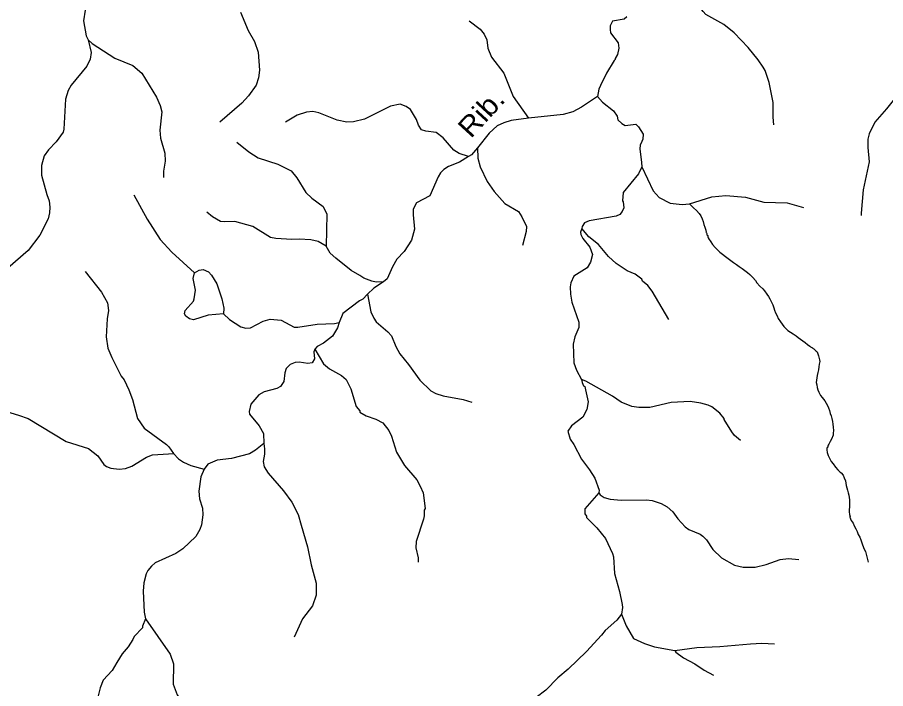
# Model space of a CAD drawing. Extents: x 346.5 to 372.4, y 7400.3 to 7428.2.
# Drawn here: x 364.068 to 367.524, y 7415.59 to 7418.262 of the extents above; entities that cross this region are included whole.
import ezdxf
from ezdxf.enums import TextEntityAlignment as Align

# ---------------------------------------------------------------- set-up
doc = ezdxf.new("R2010")
doc.units = 0
doc.header["$LTSCALE"] = 0.032
doc.layers.add('2', color=7, linetype='Continuous', lineweight=25)
doc.layers.add('7', color=7, linetype='Continuous', lineweight=25)
doc.layers.add('61', color=7, linetype='Continuous')

msp = doc.modelspace()

# ---------------------------------------------------------------- linework, layer by layer
at = {"layer": '2'}
msp.add_lwpolyline([(364.7726, 7417.2451), (364.7912, 7417.2562), (364.8071, 7417.2584), (364.8294, 7417.2489), (364.8408, 7417.2358), (364.8621, 7417.201), (364.8824, 7417.1415), (364.8905, 7417.1053), (364.8887, 7417.0818), (364.827, 7417.0764), (364.7693, 7417.0589), (364.7529, 7417.062), (364.7384, 7417.0726), (364.734, 7417.0828), (364.7354, 7417.0952), (364.7687, 7417.1326), (364.7722, 7417.142), (364.7766, 7417.1766), (364.7677, 7417.2224)], close=True, dxfattribs=at)
at = {"layer": '7'}
for points in [[(364.2254, 7418.6602), (364.2451, 7418.628), (364.2898, 7418.5793), (364.3089, 7418.5507), (364.3392, 7418.4885), (364.344, 7418.4726), (364.3551, 7418.4088), (364.3448, 7418.3195), (364.3376, 7418.2909), (364.332, 7418.2478), (364.3416, 7418.1881), (364.3499, 7418.173)], [(367.0791, 7417.8342), (367.0759, 7417.8653), (367.0759, 7417.9227), (367.0599, 7418.0024), (367.044, 7418.0502), (367.036, 7418.0645), (367.0169, 7418.0932), (366.9763, 7418.1418), (366.9213, 7418.2008), (366.8799, 7418.2335), (366.8089, 7418.2741), (366.7977, 7418.2861), (366.7762, 7418.3116), (366.7776, 7418.3454)], [(364.9568, 7418.2829), (364.9863, 7418.2096), (365.0126, 7418.1665), (365.0261, 7418.1235), (365.0325, 7418.0518), (365.0277, 7418.0215), (365.0182, 7417.9928), (364.9879, 7417.9498), (364.9616, 7417.9203), (364.8739, 7417.8454)], [(365.8669, 7418.2486), (365.91, 7418.2151), (365.9267, 7418.1952), (365.9363, 7418.1729), (365.941, 7418.1394), (365.9554, 7418.1044), (366.0048, 7418.0398), (366.0414, 7417.9466), (366.1029, 7417.8607)], [(366.4941, 7418.2645), (366.483, 7418.255), (366.4367, 7418.247), (366.4272, 7418.2287), (366.4272, 7418.2143), (366.4296, 7418.2), (366.4598, 7418.1609), (366.4622, 7418.1394), (366.4575, 7418.1147), (366.4479, 7418.0988), (366.4479, 7418.094), (366.4431, 7418.0908), (366.4136, 7418.0398), (366.3889, 7417.9912), (366.3825, 7417.9769), (366.3774, 7417.9478)], [(364.3499, 7418.173), (364.3615, 7418.1219), (364.3583, 7418.0964), (364.344, 7418.0677), (364.2826, 7417.9928), (364.2698, 7417.9705), (364.2595, 7417.937), (364.2531, 7417.8175), (364.2499, 7417.8047), (364.2228, 7417.7673), (364.1917, 7417.7354), (364.175, 7417.7107), (364.1638, 7417.6724), (364.1638, 7417.6342), (364.1854, 7417.5577), (364.1941, 7417.5322), (364.1973, 7417.5067), (364.1965, 7417.4843), (364.1909, 7417.4604), (364.1575, 7417.3951), (364.1113, 7417.3337), (364.03, 7417.2636)], [(364.3499, 7418.173), (364.3662, 7418.1584), (364.4555, 7418.1004), (364.5273, 7418.0701), (364.5631, 7418.0398), (364.6213, 7417.945), (364.6364, 7417.9115), (364.6436, 7417.886), (364.6348, 7417.8127), (364.638, 7417.7808), (364.6548, 7417.7218), (364.6564, 7417.69), (364.65, 7417.6501), (364.65, 7417.6254)], [(367.6362, 7418.1272), (367.613, 7418.0852), (367.5963, 7418.0279), (367.5716, 7417.9609), (367.5588, 7417.9378), (367.5278, 7417.8979), (367.4815, 7417.8454), (367.4584, 7417.7983), (367.4536, 7417.7776), (367.4536, 7417.7441), (367.4588, 7417.6867), (367.4345, 7417.5752), (367.4273, 7417.4828), (367.4266, 7417.474)], [(366.3774, 7417.9478), (366.314, 7417.9043), (366.279, 7417.8868), (366.2407, 7417.8756), (366.1029, 7417.8607)], [(366.3774, 7417.9478), (366.3969, 7417.9242), (366.4415, 7417.89), (366.4559, 7417.8693), (366.4582, 7417.8549), (366.4742, 7417.8398), (366.4878, 7417.8318), (366.5292, 7417.8374), (366.5411, 7417.827), (366.5595, 7417.7967), (366.5579, 7417.7768), (366.5531, 7417.7681), (366.5467, 7417.7537), (366.5451, 7417.7394), (366.5523, 7417.6843), (366.5536, 7417.6671)], [(365.8635, 7417.7084), (365.8271, 7417.7202), (365.8048, 7417.7338), (365.7633, 7417.7824), (365.7354, 7417.8039), (365.694, 7417.8087), (365.6772, 7417.8151), (365.6645, 7417.8334), (365.6573, 7417.8557), (365.6334, 7417.8948), (365.6159, 7417.9075), (365.592, 7417.9163), (365.5537, 7417.9091), (365.4501, 7417.8573), (365.4055, 7417.8461), (365.38, 7417.8453), (365.3417, 7417.8525), (365.2684, 7417.8828), (365.2445, 7417.8876), (365.219, 7417.8852), (365.1824, 7417.8732), (365.1353, 7417.8446)], [(366.1029, 7417.8607), (366.0335, 7417.8517), (366.004, 7417.843), (365.9785, 7417.831), (365.9466, 7417.8015), (365.8994, 7417.7432)], [(364.9417, 7417.7657), (364.9895, 7417.7274), (365.0261, 7417.7035), (365.1043, 7417.6772), (365.1584, 7417.6509), (365.1807, 7417.623), (365.2158, 7417.5648), (365.2397, 7417.5425), (365.2859, 7417.509), (365.3003, 7417.4788), (365.2974, 7417.351)], [(365.8994, 7417.7432), (365.8754, 7417.7156), (365.8635, 7417.7084)], [(365.8994, 7417.7432), (365.9012, 7417.7011), (365.9107, 7417.6676), (365.9386, 7417.6095), (365.9665, 7417.5688), (366.0088, 7417.521), (366.0622, 7417.4899), (366.0765, 7417.4684), (366.0941, 7417.4294), (366.0933, 7417.4094), (366.0781, 7417.3544)], [(365.8635, 7417.7084), (365.8279, 7417.6852), (365.7848, 7417.6684), (365.7657, 7417.6565), (365.7522, 7417.6437), (365.7434, 7417.6278), (365.7099, 7417.5521), (365.6565, 7417.5242), (365.6438, 7417.4987), (365.643, 7417.4764), (365.6493, 7417.419), (365.6366, 7417.376), (365.6071, 7417.3297), (365.5784, 7417.2995), (365.5609, 7417.2692), (365.5397, 7417.2213), (365.5253, 7417.2095)], [(366.5536, 7417.6671), (366.5406, 7417.6388), (366.479, 7417.5656), (366.4766, 7417.5314), (366.4798, 7417.5274), (366.4822, 7417.5043), (366.4758, 7417.4891), (366.4662, 7417.478), (366.4519, 7417.4708), (366.3443, 7417.4524), (366.3252, 7417.4437), (366.316, 7417.4302), (366.3146, 7417.422)], [(366.5536, 7417.6671), (366.5985, 7417.572), (366.6232, 7417.5449), (366.6663, 7417.5226), (366.7141, 7417.5178), (366.7433, 7417.5198)], [(364.5312, 7417.5553), (364.5846, 7417.4588), (364.6372, 7417.3775), (364.6827, 7417.3273), (364.7726, 7417.2451)], [(366.7433, 7417.5198), (366.8318, 7417.5484), (366.8878, 7417.5529), (366.9659, 7417.5465), (367.0392, 7417.5266), (367.1317, 7417.5242), (367.1978, 7417.5059)], [(366.7433, 7417.5198), (366.7595, 7417.5043), (366.7714, 7417.4939), (366.7818, 7417.482), (366.789, 7417.4716), (366.7938, 7417.4604), (366.7978, 7417.4493), (366.8009, 7417.4381), (366.8041, 7417.427), (366.8081, 7417.4158), (366.8097, 7417.4054), (366.8105, 7417.4047), (366.8129, 7417.4023), (366.8129, 7417.3967), (366.8161, 7417.3935), (366.8161, 7417.3863), (366.8193, 7417.3847), (366.8193, 7417.3823), (366.828, 7417.3688), (366.8352, 7417.3584), (366.8456, 7417.3457), (366.8543, 7417.3369), (366.8647, 7417.3281), (366.8751, 7417.3194), (366.8862, 7417.3106), (366.8974, 7417.3018), (366.9085, 7417.2939), (366.9189, 7417.2859), (366.9301, 7417.2787), (366.9412, 7417.2708), (366.9524, 7417.2628), (366.9643, 7417.2548), (366.9739, 7417.2468), (366.9834, 7417.2381), (366.9954, 7417.2269), (367.0057, 7417.2142), (367.0121, 7417.2054), (367.0233, 7417.1927), (367.0352, 7417.1815), (367.0424, 7417.1735), (367.0512, 7417.16), (367.0575, 7417.1512), (367.0631, 7417.1417), (367.0695, 7417.1281), (367.0751, 7417.1178), (367.0791, 7417.1066), (367.0823, 7417.097), (367.0862, 7417.0859), (367.0918, 7417.0747), (367.0966, 7417.0636), (367.1054, 7417.0508), (367.1117, 7417.0412), (367.1189, 7417.0317), (367.1269, 7417.0237), (367.1349, 7417.0157), (367.1452, 7417.0094), (367.1564, 7417.0022), (367.1675, 7416.995), (367.1763, 7416.9886), (367.1859, 7416.9815), (367.1946, 7416.9751), (367.2042, 7416.9687), (367.213, 7416.9607), (367.2225, 7416.9536), (367.2257, 7416.9512), (367.2281, 7416.9496), (367.2305, 7416.948), (367.2321, 7416.9472), (367.2337, 7416.9464), (367.2361, 7416.944), (367.2377, 7416.9432), (367.2456, 7416.936), (367.2472, 7416.9337), (367.2512, 7416.9305), (367.2528, 7416.9265), (367.2568, 7416.9153), (367.2592, 7416.9042), (367.2608, 7416.8994), (367.2616, 7416.893), (367.26, 7416.8819), (367.2584, 7416.8707), (367.2568, 7416.8595), (367.2544, 7416.8484), (367.252, 7416.8372), (367.2496, 7416.8277), (367.2488, 7416.8181), (367.248, 7416.8085), (367.2496, 7416.799), (367.2512, 7416.7894), (367.2536, 7416.7798), (367.2584, 7416.7703), (367.2648, 7416.7575), (367.2711, 7416.7496), (367.2815, 7416.736), (367.2871, 7416.7272), (367.2927, 7416.7177), (367.2966, 7416.7081), (367.3006, 7416.697), (367.3038, 7416.6858), (367.307, 7416.6762), (367.3102, 7416.6651)], [(365.2974, 7417.351), (365.2652, 7417.3696), (365.2365, 7417.3767), (365.1903, 7417.3799), (365.16, 7417.3775), (365.0963, 7417.3815), (365.0756, 7417.3855), (365.0054, 7417.4301), (364.9337, 7417.4493), (364.8907, 7417.4477), (364.8763, 7417.4501), (364.8444, 7417.4684), (364.8221, 7417.4867)], [(366.3146, 7417.422), (366.3098, 7417.4075), (366.3105, 7417.3985), (366.3191, 7417.3824), (366.3467, 7417.3473), (366.3578, 7417.3186), (366.3491, 7417.2883), (366.3355, 7417.2652), (366.2829, 7417.2317), (366.271, 7417.2054), (366.2678, 7417.1895), (366.2694, 7417.1608), (366.2757, 7417.1289), (366.3028, 7417.0492), (366.3028, 7417.0277), (366.2869, 7416.9902), (366.2805, 7416.9615), (366.2837, 7416.8866), (366.2941, 7416.8579), (366.3133, 7416.8207)], [(366.6607, 7417.0596), (366.5953, 7417.1719), (366.5778, 7417.1951), (366.5563, 7417.2126), (366.5531, 7417.2205), (366.5276, 7417.2397), (366.4957, 7417.2532), (366.4511, 7417.2819), (366.4216, 7417.3106), (366.3817, 7417.3576), (366.3424, 7417.3882), (366.3146, 7417.422)], [(365.5253, 7417.2095), (365.4957, 7417.2082), (365.4788, 7417.2118), (365.4469, 7417.2237), (365.431, 7417.2341), (365.3967, 7417.254), (365.3362, 7417.3034), (365.3138, 7417.3241), (365.2974, 7417.351)], [(364.3384, 7417.2508), (364.4029, 7417.1688), (364.4268, 7417.1265), (364.4308, 7417.0954), (364.426, 7417.062), (364.4221, 7416.9902), (364.4284, 7416.9456), (364.4436, 7416.9082), (364.4818, 7416.834), (364.4938, 7416.8189), (364.5121, 7416.7798), (364.5265, 7416.7416), (364.5464, 7416.6651), (364.5727, 7416.6276), (364.6611, 7416.5623), (364.6715, 7416.5527), (364.6893, 7416.5267)], [(365.5253, 7417.2095), (365.4876, 7417.1839), (365.462, 7417.1606)], [(365.462, 7417.1606), (365.443, 7417.1408), (365.4294, 7417.1345), (365.364, 7417.0835), (365.349, 7417.0473)], [(365.462, 7417.1606), (365.4748, 7417.0898), (365.4868, 7417.0652), (365.4963, 7417.0508), (365.5426, 7417.0109), (365.5577, 7416.9942), (365.5744, 7416.952), (365.5904, 7416.9233), (365.6254, 7416.881), (365.6701, 7416.8181), (365.7139, 7416.7758), (365.7338, 7416.7655), (365.7625, 7416.7559), (365.8422, 7416.7416), (365.8765, 7416.7304)], [(364.8887, 7417.0818), (364.9129, 7417.0597), (364.957, 7417.0307), (364.9769, 7417.0245), (364.9959, 7417.0269), (365.0461, 7417.0524), (365.074, 7417.0604), (365.1186, 7417.0572), (365.1696, 7417.0293), (365.184, 7417.0285), (365.2621, 7417.0404), (365.3308, 7417.0434), (365.349, 7417.0473)], [(365.349, 7417.0473), (365.3425, 7417.0269), (365.3226, 7416.9934), (365.2868, 7416.9655), (365.262, 7416.9528), (365.2528, 7416.9409)], [(363.6953, 7416.9958), (363.7263, 7416.9631), (363.7566, 7416.9368), (363.7781, 7416.9121), (363.8467, 7416.8045), (363.8682, 7416.7822), (363.9327, 7416.7352), (363.9582, 7416.7185), (363.9965, 7416.7009), (364.073, 7416.6794), (364.1113, 7416.6651), (364.2627, 7416.5734), (364.3519, 7416.5463), (364.3886, 7416.5168), (364.4117, 7416.4826), (364.4228, 7416.4746), (364.4404, 7416.4682), (364.4731, 7416.4642), (364.4986, 7416.4666), (364.5241, 7416.4754), (364.5815, 7416.5113), (364.6054, 7416.5216), (364.6691, 7416.5248), (364.6893, 7416.5267)], [(365.2528, 7416.9409), (365.248, 7416.9306), (365.2509, 7416.9034), (365.2413, 7416.8874), (365.2238, 7416.885), (365.1903, 7416.8898), (365.1744, 7416.8882), (365.1536, 7416.8803), (365.1385, 7416.8643), (365.1329, 7416.8468), (365.1282, 7416.8125), (365.1154, 7416.7926), (365.1011, 7416.7854), (365.0501, 7416.7719), (365.0293, 7416.7599), (364.9974, 7416.7225), (364.9911, 7416.6938), (364.9927, 7416.6834), (365.0309, 7416.6364), (365.0485, 7416.6053), (365.0486, 7416.5655)], [(365.2528, 7416.9409), (365.2867, 7416.8826), (365.3099, 7416.8627), (365.3577, 7416.8364), (365.3768, 7416.8213), (365.3959, 7416.783), (365.4166, 7416.7129), (365.431, 7416.6962), (365.431, 7416.6906), (365.4565, 7416.6762), (365.4948, 7416.6635), (365.5226, 7416.6483), (365.5465, 7416.6173), (365.5577, 7416.595), (365.5776, 7416.5312), (365.6095, 7416.4786), (365.6581, 7416.4212), (365.6717, 7416.3957), (365.6828, 7416.3702), (365.6908, 7416.3073), (365.6876, 7416.3009), (365.6876, 7416.2778), (365.6844, 7416.265), (365.6549, 7416.1758), (365.6541, 7416.1503), (365.6629, 7416.1104), (365.6637, 7416.0937)], [(366.3133, 7416.8207), (366.3167, 7416.809), (366.3215, 7416.7959), (366.3268, 7416.7934), (366.3299, 7416.7798), (366.3403, 7416.732), (366.3347, 7416.7017), (366.3188, 7416.6706), (366.2742, 7416.6364), (366.2598, 7416.6157), (366.2678, 7416.583), (366.2829, 7416.5615), (366.314, 7416.5041), (366.3459, 7416.4619), (366.3666, 7416.4276), (366.3837, 7416.3807), (366.383, 7416.3697)], [(366.946, 7416.5782), (366.9229, 7416.5981), (366.9117, 7416.6125), (366.8814, 7416.6611), (366.8814, 7416.6659), (366.8639, 7416.6874), (366.832, 7416.7121), (366.8177, 7416.7185), (366.789, 7416.7272), (366.746, 7416.7336), (366.6711, 7416.7296), (366.585, 7416.7089), (366.5419, 7416.7089), (366.5133, 7416.7137), (366.471, 7416.7304), (366.4367, 7416.7543), (366.3303, 7416.8147), (366.3133, 7416.8207)], [(367.3102, 7416.6651), (367.3126, 7416.6539), (367.3142, 7416.6428), (367.3158, 7416.6316), (367.3166, 7416.6181), (367.315, 7416.6077), (367.315, 7416.5981), (367.3134, 7416.5965), (367.3102, 7416.5854), (367.3038, 7416.5742), (367.2974, 7416.5631), (367.2958, 7416.5591), (367.2942, 7416.5551), (367.2935, 7416.5519), (367.2919, 7416.5495), (367.2903, 7416.5463), (367.2903, 7416.5408), (367.2919, 7416.5296), (367.295, 7416.5184), (367.3006, 7416.5073), (367.3078, 7416.4945), (367.315, 7416.485), (367.3245, 7416.4714), (367.3333, 7416.4611), (367.3365, 7416.4587), (367.3421, 7416.4531), (367.3437, 7416.4523), (367.3476, 7416.4499), (367.3548, 7416.4403), (367.3596, 7416.4292), (367.3644, 7416.418), (367.366, 7416.4085), (367.3676, 7416.3989), (367.37, 7416.3893), (367.3723, 7416.3798), (367.3755, 7416.3702), (367.3779, 7416.3607), (367.3795, 7416.3511), (367.3803, 7416.3415), (367.3803, 7416.332), (367.3803, 7416.3224), (367.3803, 7416.3128), (367.3795, 7416.3033), (367.3795, 7416.2937), (367.3803, 7416.2841), (367.3827, 7416.2738), (367.3819, 7416.273), (367.3875, 7416.2594), (367.3947, 7416.2491), (367.3994, 7416.2379), (367.4058, 7416.2268), (367.4106, 7416.2156), (367.4154, 7416.2045), (367.4218, 7416.1933), (367.4249, 7416.1821), (367.4297, 7416.171), (367.4377, 7416.1487), (367.4441, 7416.1359), (367.4543, 7416.0941)], [(365.0486, 7416.5655), (365.0166, 7416.5391), (364.9927, 7416.5248), (364.921, 7416.5065), (364.8636, 7416.5001), (364.8269, 7416.4842), (364.8115, 7416.4644)], [(365.0486, 7416.5655), (365.0524, 7416.5455), (365.0524, 7416.5232), (365.0469, 7416.4945), (365.05, 7416.473), (365.0668, 7416.4475), (365.1281, 7416.3782), (365.1608, 7416.332), (365.1863, 7416.2841), (365.1983, 7416.2411), (365.223, 7416.155), (365.2373, 7416.0833), (365.2573, 7416.01), (365.2573, 7415.9622), (365.2429, 7415.9199), (365.2031, 7415.8681), (365.1704, 7415.7956)], [(364.6893, 7416.5267), (364.7098, 7416.5049), (364.7289, 7416.4913), (364.7584, 7416.4786), (364.8115, 7416.4644)], [(364.8115, 7416.4644), (364.799, 7416.434), (364.7902, 7416.3758), (364.7934, 7416.3463), (364.8046, 7416.3081), (364.807, 7416.2826), (364.8014, 7416.2427), (364.795, 7416.2236), (364.7791, 7416.1957), (364.7265, 7416.1463), (364.6994, 7416.1287), (364.6165, 7416.0913), (364.6014, 7416.0785), (364.5878, 7416.0602), (364.5814, 7416.0474), (364.5719, 7416.0116), (364.5695, 7415.9781), (364.5727, 7415.8952), (364.5788, 7415.8682)], [(366.383, 7416.3697), (366.3268, 7416.3057), (366.3268, 7416.2857), (366.3331, 7416.277), (366.3331, 7416.2722), (366.3746, 7416.2299), (366.4088, 7416.1885), (366.4375, 7416.1279), (366.4407, 7416.1152), (366.4447, 7416.0482), (366.4646, 7415.9765), (366.475, 7415.9255), (366.4766, 7415.9128), (366.4729, 7415.8864)], [(366.383, 7416.3697), (366.3882, 7416.3614), (366.4041, 7416.3511), (366.4272, 7416.3439), (366.4718, 7416.3399), (366.5722, 7416.3423), (366.5945, 7416.3391), (366.6312, 7416.3272), (366.6551, 7416.3136), (366.6774, 7416.2937), (366.6965, 7416.2666), (366.726, 7416.2339), (366.7404, 7416.2236), (366.7858, 7416.2052), (366.797, 7416.1973), (366.8105, 7416.1829), (366.8368, 7416.1439), (366.8703, 7416.1112), (366.9229, 7416.0817), (366.9564, 7416.0737), (367.0042, 7416.0737), (367.0488, 7416.0849), (367.1046, 7416.104), (367.1381, 7416.1088), (367.1787, 7416.104)], [(364.5788, 7415.8682), (364.5658, 7415.8393), (364.5663, 7415.8323), (364.5336, 7415.798), (364.5272, 7415.7853), (364.5097, 7415.7566), (364.485, 7415.7287), (364.4635, 7415.6944), (364.446, 7415.6625), (364.4093, 7415.6235), (364.3973, 7415.594), (364.3902, 7415.5621)], [(364.5788, 7415.8682), (364.6763, 7415.7271), (364.689, 7415.6888), (364.6882, 7415.6083), (364.7042, 7415.5653), (364.7352, 7415.5175), (364.7751, 7415.4808), (364.8014, 7415.4513), (364.8134, 7415.4346), (364.8309, 7415.3924)], [(366.4729, 7415.8864), (366.4536, 7415.8623), (366.408, 7415.8219), (366.3929, 7415.8036), (366.3339, 7415.7382), (366.2606, 7415.6681), (366.22, 7415.6338), (366.1722, 7415.5844), (366.1337, 7415.5549)], [(366.4729, 7415.8864), (366.4909, 7415.841), (366.5204, 7415.79), (366.5643, 7415.7701), (366.6041, 7415.7573), (366.6849, 7415.7422)], [(366.6849, 7415.7422), (366.7731, 7415.7542), (366.8639, 7415.7581), (366.9866, 7415.7693), (367.0313, 7415.7717), (367.0815, 7415.7693)], [(366.6849, 7415.7422), (366.6889, 7415.7354), (366.7197, 7415.7127), (366.7643, 7415.6896), (366.8017, 7415.6641), (366.8392, 7415.6434)]]:
    msp.add_lwpolyline(points, dxfattribs=at)

# ---------------------------------------------------------------- texts
at = {"layer": '61', "width": 1.1}
msp.add_text('Rib.', height=0.08, rotation=47.481, dxfattribs=at).set_placement((365.944, 7417.8542), align=Align.CENTER)

doc.saveas('drawing.dxf')
